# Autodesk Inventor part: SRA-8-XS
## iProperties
Author: ARennick
Shininess: 20.0
PropertySet Name: _Private Model Information
Created: 2001-03
Part Number: SRA-8-XS
Document SubType Name: Modeling
Designer: ARennick
Description: SRA-8-XS x 8in
Vendor: Thomson Ind.
Control State: 0
Master: False
Checked Out: False
PropertySet Name: Design Tracking Control
Density: 0.0
Volumn: 0.0
Area: 0.0
PropertySet Name: Model Information
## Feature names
1. Extrusion1
2. Extrusion2
3. Hole2
4. Rectangular Pattern3
